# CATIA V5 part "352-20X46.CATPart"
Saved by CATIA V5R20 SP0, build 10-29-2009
Part number: 352-20X46
Definition: NONE
Nomenclature: 352-20X46
Source: Unknown
Description: 352-20X46
Bounding box of the stored display mesh (mm): x 0 to 46, y -14 to 14, z -14 to 14
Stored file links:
  C:\Users\Utente\Desktop\IO LAVORO\3D X SITO CF\X SITO\PLASTICA\352\352-20X46.CATPart
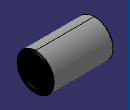
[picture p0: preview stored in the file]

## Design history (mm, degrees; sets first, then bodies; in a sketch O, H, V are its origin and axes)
Body1 "352-20X46" (main body)
  Solid1: solid without history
